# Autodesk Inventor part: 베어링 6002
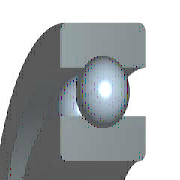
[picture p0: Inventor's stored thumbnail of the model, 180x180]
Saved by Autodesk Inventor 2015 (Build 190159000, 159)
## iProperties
IsCustomPart: 0
Created: 2012-02
Part Number: 베어링 6002
Material: 강철, 연강
Description: 깊은 그루브 볼 베어링
Document SubType Name: Modeling
Standard: KS B 2023
Designer: mduedu
Standards Organization: KS
Language: ko-KR
Size Designation: 6002 - 15 x 32 x 9
Categories: <MemberInstance><Categories><Category DisplayName="샤프트 부품" InternalName="7f7aeb1f-a693-4053-b835-cee3144e0d98" Mnemonic="SHFT"><Category DisplayName="베어링" Inter
Density: 7.86 g/cm^3
Mass: 29.8124 g
Surface Area: 39.9079 cm^2
Volume: 3.79293 cm^3
Appearance: 노란색
Author: mduedu
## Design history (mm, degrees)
sketch "스케치" dims "d0" = 4.42 (= -0.26 x WD + 0.26 x BD)
  geometry: L1 (2.29, 11.75)-(6.71, 11.75); L2 (4.5, 11.75)-(4.5, 9.54); L3 (4.5, 11.75)-(4.5, 13.96); L4 (2.858, 10.271)-(0, 10.271); L5 (0, 7.5)-(9, 7.5); L6 (2.858, 13.229)-(0, 13.229); L7 (0, 16)-(9, 16); L8 (9, 7.5)-(9, 10.271); L9 (6.142, 10.271)-(9, 10.271); L10 (6.142, 13.229)-(9, 13.229); L11 (9, 16)-(9, 13.229); L12 (-1.4, 0)-(8.4, 0) reference; L13 (0, -0.3)-(0, 5.3) reference
  constraints: 22 end point, 4 point on line, 2 collinear, 2 perpendicular, 2 symmetric about line, 1 midpoint, 1 parallel, 14 other
  dimensions: "d9" = 15 diameter of L5 L12 (= WD); "d11" = 32 diameter of L7 L12 (= BD); "d12" = 9 distance between parallel lines of L8 L13 (= KB); "d13" = 20.542 diameter of L9 L12 (= 0.326 x BD + 0.674 x WD)
revolve "본체" stored, may be unused: angle "d6" = 90 deg
revolve "볼" stored, may be unused: angle "d7" = 90 deg
pattern_circular "IDS_ARRAYBALL[SIMPL:T]" dims angle "d3" = 360 deg
body "Solid1"
fillet "모깎기1" dims "d1" = 0.3 (= KRS)
other parameters: "WD" = 15 [user parameter; used in 5 equation terms], "BD" = 32 [user parameter; used in 5 equation terms], "KB" = 9 [user parameter; used in 1 equation term], "KRS" = 0.3 [user parameter; used in 1 equation term], "d4" = 0, "d5" = 0, "d8" = 0, "d14" = 0, "d15" = 0, "BBA" = 0 [user parameter], "BC0" = 2850000 [user parameter], "BC" = 5590000 [user parameter], "BR" = 16 (= 0.5 x BD) [user parameter], "WR" = 7.5 (= 0.5 x WD) [user parameter]
